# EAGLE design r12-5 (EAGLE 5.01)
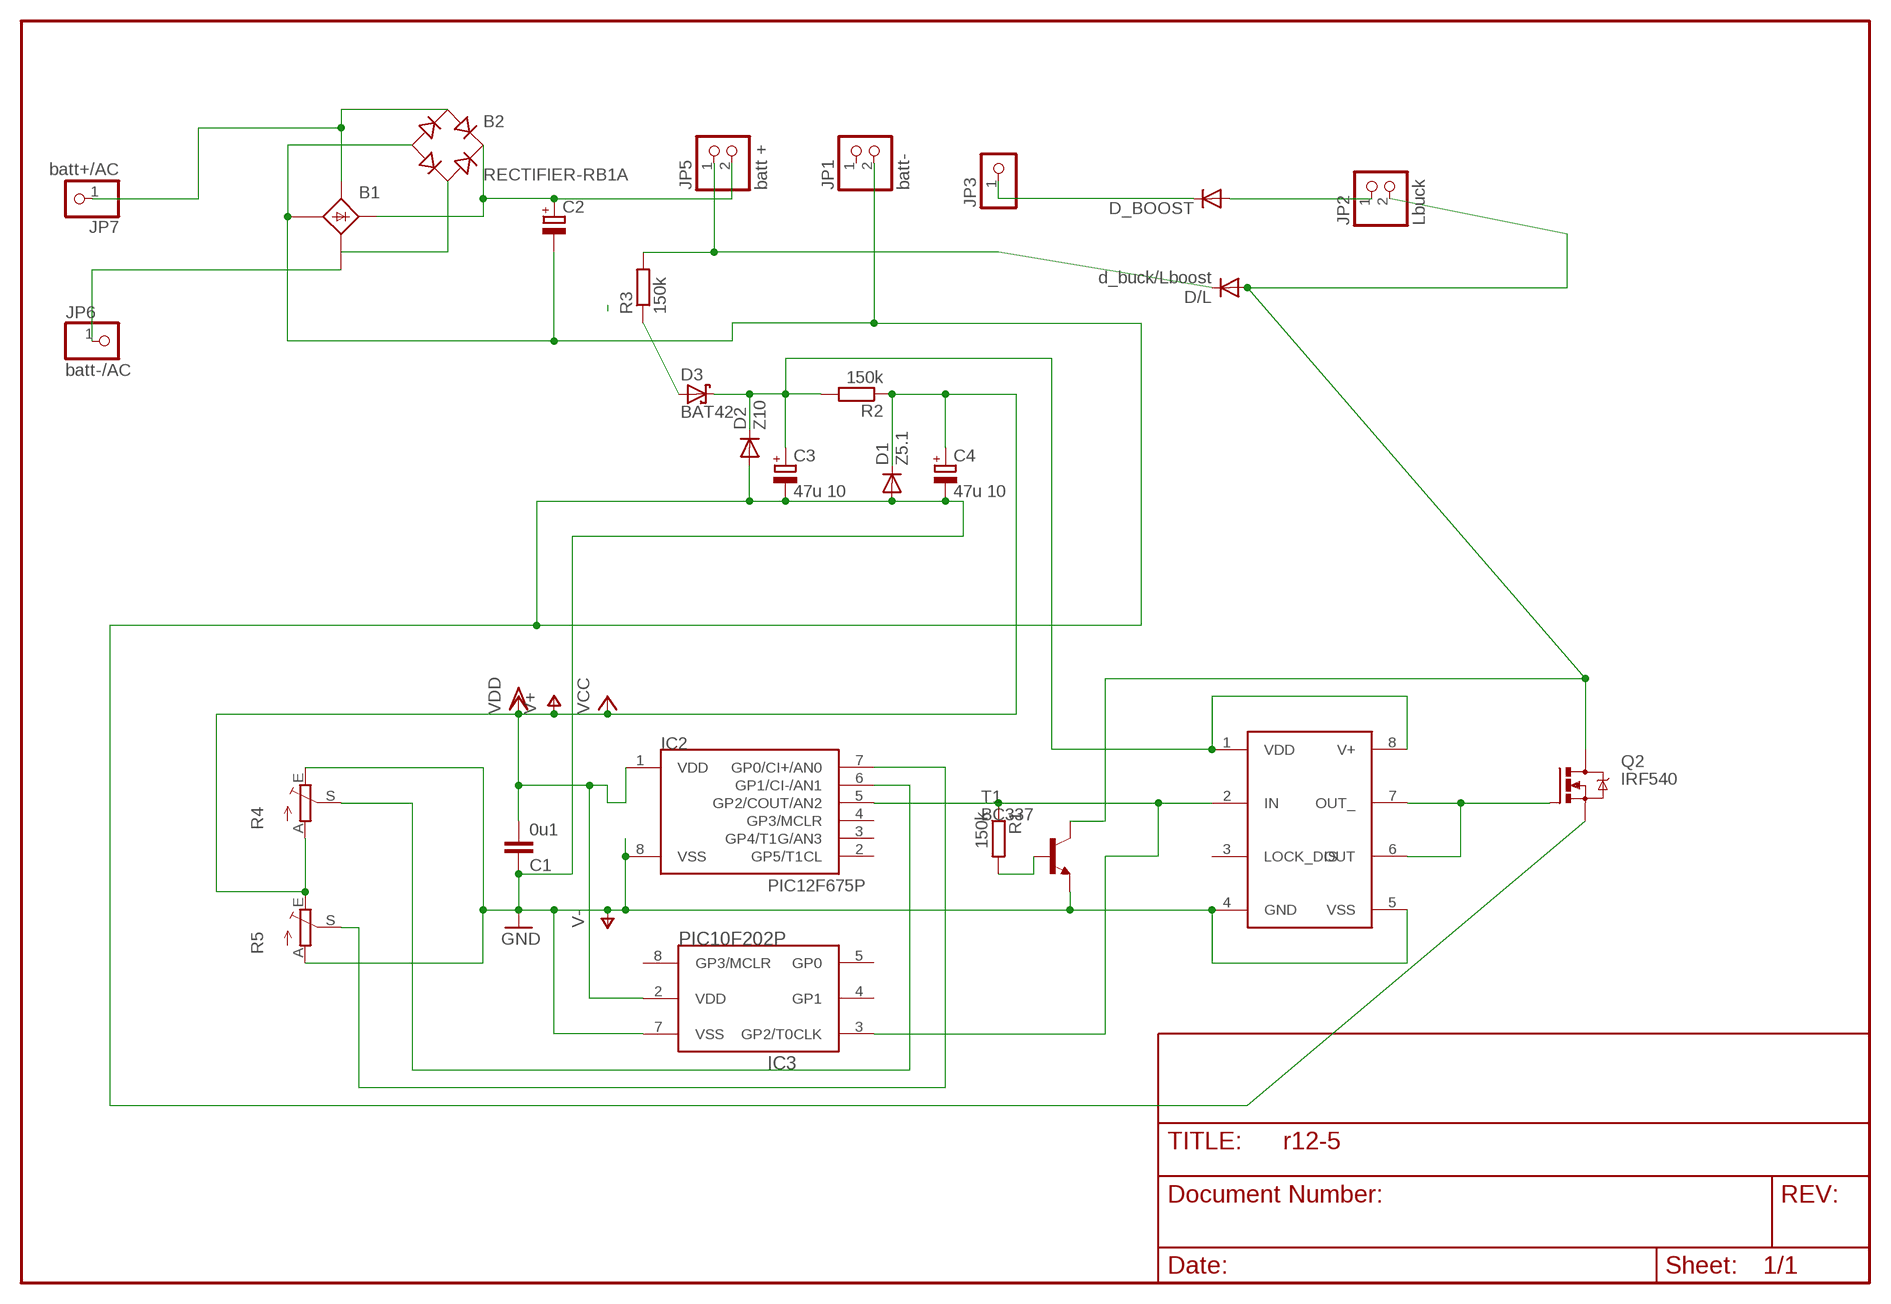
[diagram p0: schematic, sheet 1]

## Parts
B1  B25A-  [B25A-]
B2  RECTIFIER-RB1A  [RB1A]
C1  0u1  C-EU050-025X075  [C050-025X075]
C2  CPOL-EUE7.5-18  [E7,5-18]
C3  47u 10  CPOL-EUE2,5-6E  [E2,5-6E]
C4  47u 10  CPOL-EUE2.5-6  [E2,5-6]
D1  Z5.1  DIODE-D-7.5  [D-7.5]
D2  Z10  DIODE-D-7.5  [D-7.5]
D3  BAT42  [DO35-10]
D/L  d_buck/Lboost  DIODE-D-7.5  [D-7.5]
D_BOOST  DIODE-D-5  [D-5]
IC1  TC4432X  [SO-08]
IC2  PIC12F675P  [DIL8]
IC3  PIC10F202P  [DIL8]
JP1  batt-  PINHD-1X2  [1X02]
JP2  Lbuck  PINHD-1X2  [1X02]
JP3  PINHD-1X1  [1X01]
JP5  batt +  PINHD-1X2  [1X02]
JP6  batt-/AC  PINHD-1X1  [1X01]
JP7  batt+/AC  PINHD-1X1  [1X01]
Q2  IRF540  [TO220BV]
R1  150k  R-EU_0207/15  [0207/15]
R2  150k  R-EU_0204/7  [0204/7]
R3  150k  R-EU_0204/7  [0204/7]
R4  TRIM_EU-CA6V  [CA6V]
R5  TRIM_EU-CA6V  [CA6V]
T1  BC337  [TO92]

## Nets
LOAD: D_BOOST.C JP3.1
N$1: D/L.C JP5.1 R3.2
N$3: B1.AC2-(AC2) JP6.1
N$4: C3.+ D2.C D3.C IC1.1(VDD) IC1.8(V+) R2.2
N$5: D_BOOST.A JP2.1
N$6: R1.2 T1.2(B)
N$7: IC1.6(OUT) IC1.7(OUT_) Q2.G
N$8: B1.AC1 B2.AC1 JP7.1
N$9: D/L.A JP2.2 Q2.D T1.3(C)
N$10: B1.+ B2.+ C2.+ JP5.2
N$11: B1.AC2 B2.AC2
N$13: IC2.7(GP0/CI+/AN0) R5.S
N$14: IC1.2(IN) IC2.5(GP2/COUT/AN2) IC3.3(GP2/T0CLK) R1.1
N$15: IC2.6(GP1/CI-/AN1) R4.S
N$17: D3.A R3.1
V+: C1.2 C4.+ D1.C IC2.1(VDD) IC3.2(VDD) R2.1 R4.A R5.E ; supply symbol labelled VCC, VDD
V-: B1.-1(-) B2.- C1.1 C2.- C3.- C4.- D1.A D2.A IC1.4(GND) IC1.5(VSS) IC2.8(VSS) IC3.7(VSS) JP1.2 Q2.S R4.E R5.A T1.1(E) ; supply symbol labelled GND
Unconnected: B1.+1(+) B1.- B1.AC1-(AC1) IC1.3(LOCK_DIS) IC2.2(GP5/T1CL) IC2.3(GP4/T1G/AN3) IC2.4(GP3/MCLR) IC3.4(GP1) IC3.5(GP0) IC3.8(GP3/MCLR) JP1.1

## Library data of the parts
B1 = rectifier:B25A-: RECTIFIER 25-A bridge
B2 = rectifier:RECTIFIER-: Rectifier
C1 = rcl:C-EU: CAPACITOR, European symbol
C2-C4 = rcl:CPOL-EU: POLARIZED CAPACITOR, European symbol
D1 D2 D/L D_BOOST = diode:DIODE-: DIODE
D3 = diode-1:BAT42: DIODE
IC1 = microchip:TC4432
IC2 = microchip-3:PIC12F6*: uPC nW 1k Program Flash memory 2x Timer Comparator 10b A/D converter/ 4xIN
IC3 = microchip-3:PIC10F20*: uPC nW 0,25/0,5k Program Flash memory
JP1 JP2 JP5 = pinhead:PINHD-1X2: PIN HEADER
JP3 JP6 JP7 = pinhead:PINHD-1X1: PIN HEADER
Q2 = transistor-power:IRF540: HEXFET Power MOSFET
R1-R3 = rcl:R-EU_: RESISTOR, European symbol
R4 R5 = pot:TRIM_EU-: POTENTIOMETER
T1 = transistor-neu-to92:BC337: NPN TRANSISTOR

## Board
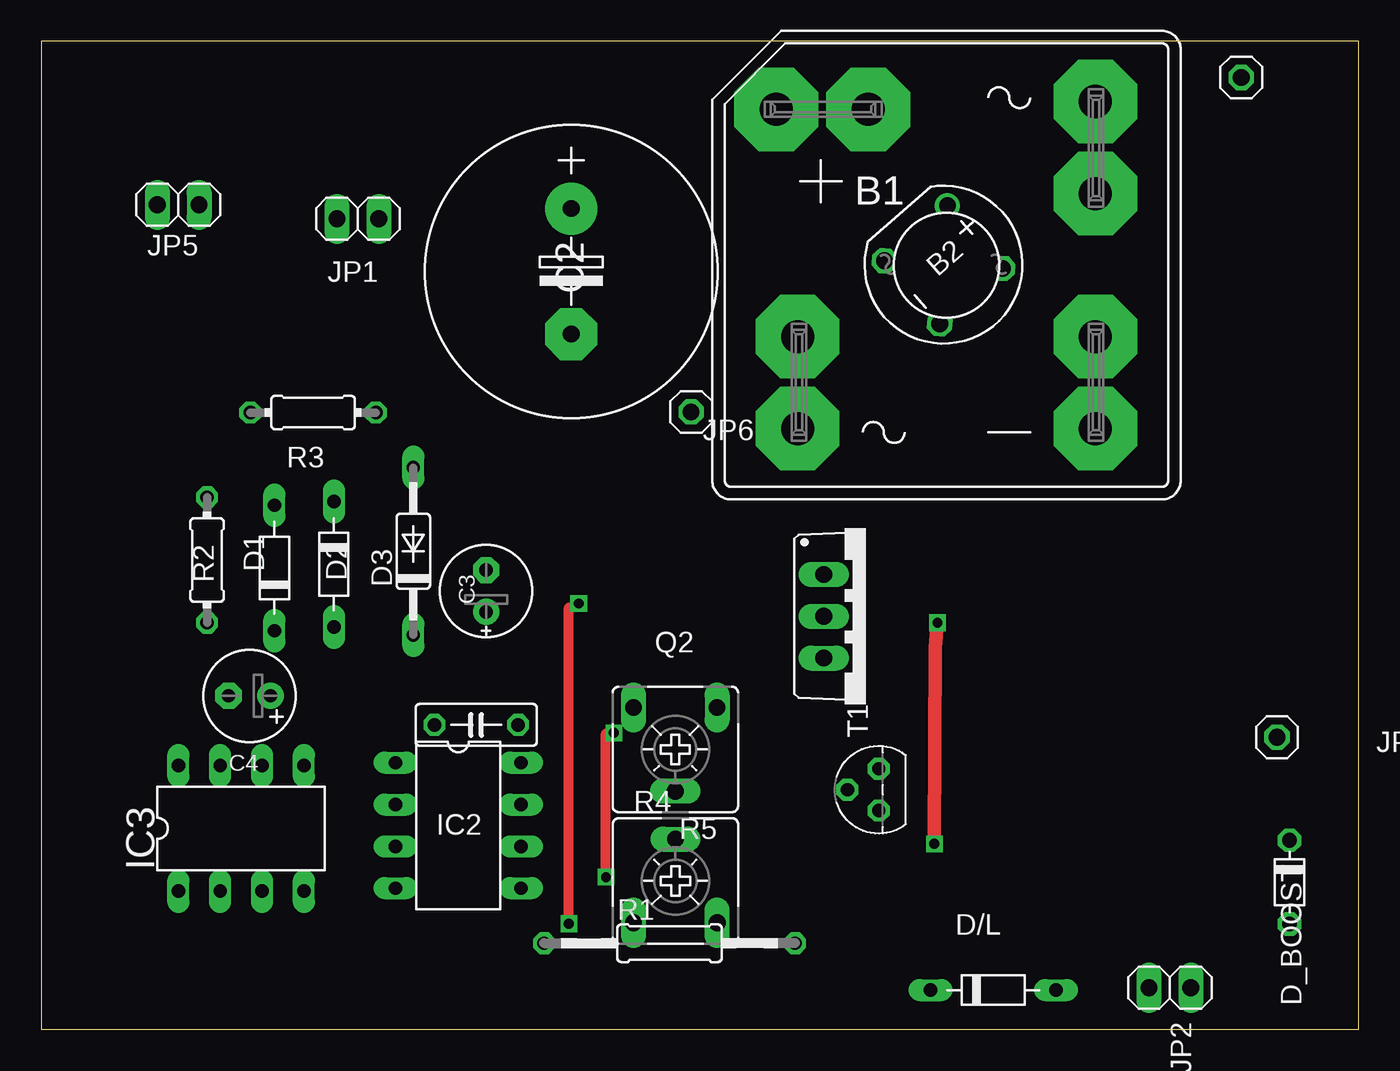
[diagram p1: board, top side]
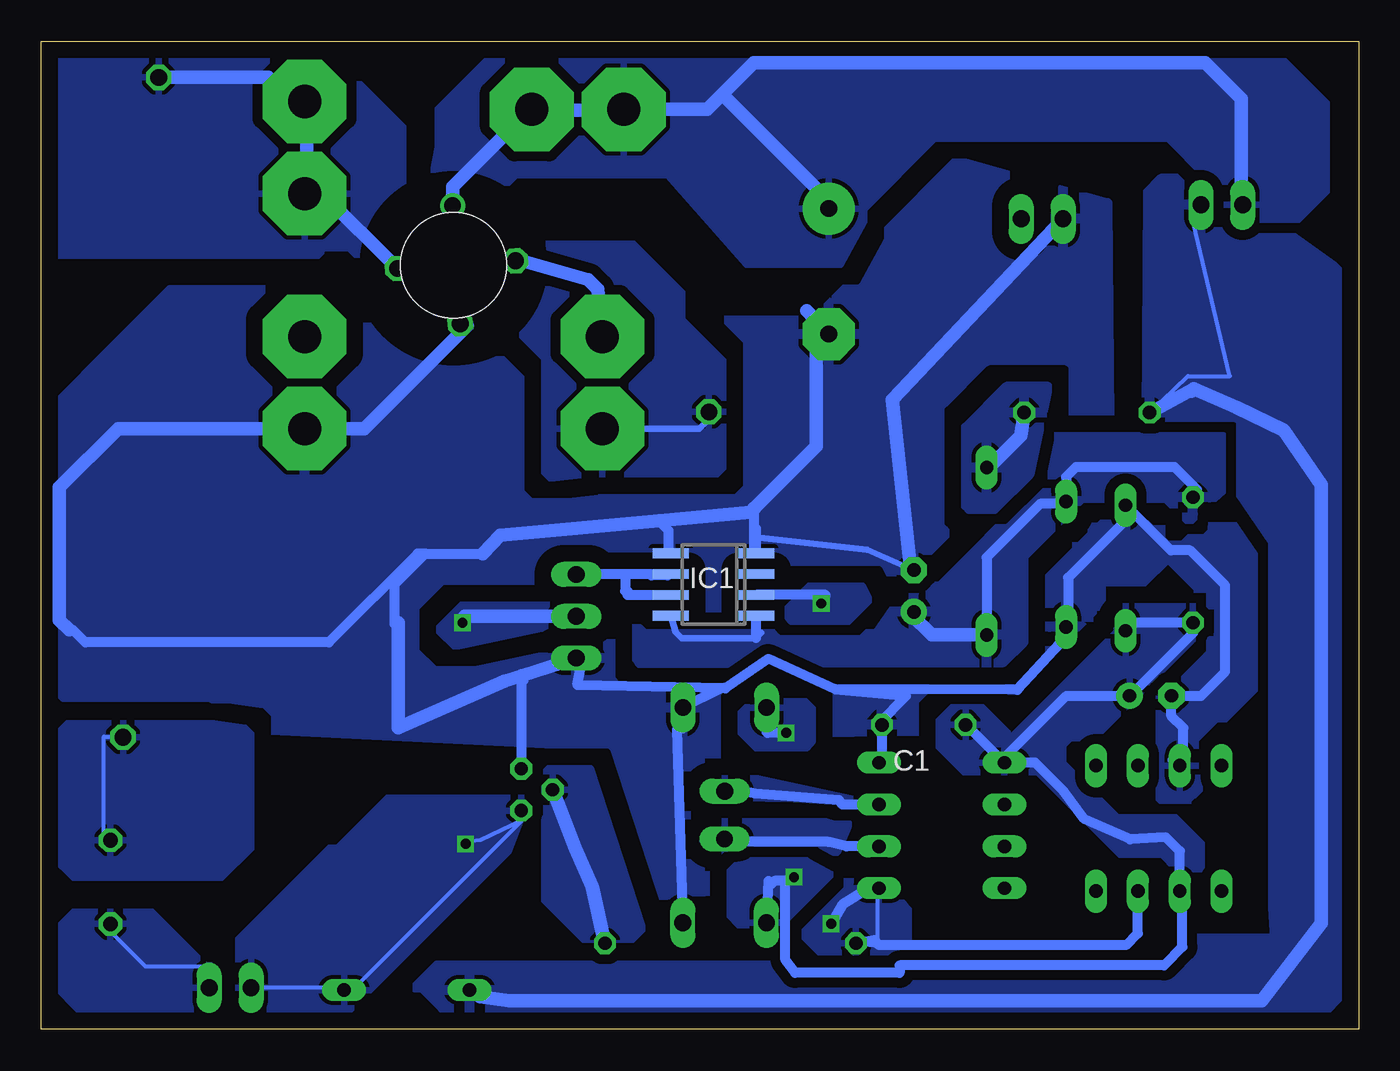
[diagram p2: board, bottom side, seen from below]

Size 80 x 60 mm. Coordinates in mm from the lower left corner, seen from the top.
Outline: 0,0 80,0 80,60 0,60 0,0
Copper layers (1*16): Top 0.035mm / dielectric 1.5mm / Bottom 0.035mm
Design rules "default": minimum track width 10mil, minimum drill 24mil, track to track 8mil, track to pad 8mil, pad to pad 8mil, via to via 8mil, smd to smd 8mil, copper to edge 40mil, drill to drill 8mil, minimum pad ring 10mil, minimum via ring 8mil, stop-mask expansion 4mil, vias tented up to drill 0mil, thermal gap 10mil

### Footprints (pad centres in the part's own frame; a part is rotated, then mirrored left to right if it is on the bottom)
B25A- = drill 2.007 pad 5.08 octagon: + -10.338,9.449; +1 -4.75,9.449; - 9.042,-4.343; -1 9.042,-9.931; AC1 9.042,4.343; AC1- 9.042,9.931; AC2 -9.042,-4.343; AC2- -9.042,-9.931 | hole 6.401: 0,0
RB1A = drill 1.016 round: + -2.54,2.54 | drill 1.016 octagon: - 2.54,-2.54; AC1 2.54,2.54; AC2 -2.54,-2.54
C050-025X075 = drill 0.813 octagon: 1 -2.54,0; 2 2.54,0
E7,5-18 = drill 1.016 pad 3.15 round: + -3.81,0 | drill 1.016 pad 3.15 octagon: - 3.81,0
E2,5-6E = drill 0.813 pad 1.575 round: + -1.27,0 | drill 0.813 pad 1.575 octagon: - 1.27,0
E2,5-6 = drill 0.813 pad 1.6 round: + -1.27,0 | drill 0.813 pad 1.6 octagon: - 1.27,0
D-7.5 = drill 0.813 long: A 3.81,0; C -3.81,0
DO35-10 = drill 0.813 long: A 5.08,0; C -5.08,0
D-5 = drill 0.9 octagon: A 2.54,0; C -2.54,0
SO-08 = smd 0.6 x 2.2: 1 -1.905,-2.6; 2 -0.635,-2.6; 3 0.635,-2.6; 4 1.905,-2.6; 5 1.905,2.6; 6 0.635,2.6; 7 -0.635,2.6; 8 -1.905,2.6
DIL8 = drill 0.813 long: 1 -3.81,-3.81; 2 -1.27,-3.81; 3 1.27,-3.81; 4 3.81,-3.81; 5 3.81,3.81; 6 1.27,3.81; 7 -1.27,3.81; 8 -3.81,3.81
1X02 = drill 1.016 long: 1 -1.27,0; 2 1.27,0
1X01 = drill 1.016 octagon: 1 0,0
TO220BV = drill 1.016 long: D 0,-2.54; G -2.54,-2.54; S 2.54,-2.54
0207/15 = drill 0.813 octagon: 1 -7.62,0; 2 7.62,0
0204/7 = drill 0.813 octagon: 1 -3.81,0; 2 3.81,0
CA6V = drill 1.016 long: A -2.54,-2.54; E 2.54,-2.54; S 0,2.54
TO92 = drill 0.813 octagon: 1 1.27,0; 2 0,1.905; 3 -1.27,0

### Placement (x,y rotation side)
B1  54.97,46.41 0 top
B2  54.79,46.43 311.3 top
C1  26.42,18.49 180 top
C2  32.18,46.02 270 top
C3  27.01,26.62 90 top
C4  12.65,20.26 180 top
D1  14.16,28.02 90 top
D2  17.77,28.24 270 top
D3  22.59,29.03 90 top
D/L  57.8,2.39 0 top
D_BOOST  75.79,8.94 270 top
IC1  39.18,27.01 90 bottom
IC2  25.32,12.38 270 top
IC3  12.14,12.2 0 top
JP1  19.23,49.21 180 top
JP2  68.53,2.53 180 top
JP3  75.03,17.74 0 top
JP5  8.32,50.06 180 top
JP6  39.46,37.49 0 top
JP7  72.86,57.8 0 top
Q2  50.05,25.08 270 top
R1  38.15,5.23 0 top
R2  10.07,28.5 90 top
R3  16.51,37.45 180 top
R4  38.51,9.02 0 top
R5  38.5,17 180 top
T1  50.85,14.55 90 top

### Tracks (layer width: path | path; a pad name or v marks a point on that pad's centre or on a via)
LOAD
  Bottom 0.254: D_BOOST.C 76.2,11.43 76.2,17.78 74.93,17.78 JP3.1
  pour Bottom: 69.52,18.59 78.41,18.59 79.34,17.67 79.34,10.46 78.07,9.19 69.02,9.19 67.26,10.96 67.26,17.96 67.61,18.31
N$1
  Bottom 0.254: JP5.1 10.16,49.53 7.84,39.66 10.38,39.66 R3.2
  Bottom 0.813: D/L.C 53.34,1.97 51.58,1.73 5.91,1.73 2.29,6.44 2.29,33.06 4.55,36.37 7.46,37.78 10.02,38.89 | 10.02,38.89 10.17,38.73 | 10.02,38.89 R3.2
  pour Bottom (isolate 0.61, rank 3): 8.95,51.64 12.01,51.64 12.83,50.83 12.9,37.01 10.08,36.31 8.46,34.33 5.22,29.62 5.22,7.4 5.09,5.5 12.42,5.5 14.05,3.87 55.98,3.87 57.3,2.55 56.91,2.55 54.56,0.2 2.96,0.2 0.3,2.86 0.3,45.12 1.52,46.34
N$3
  Bottom 0.406: JP6.1 39.04,37.49 40.06,36.47 B1.AC2-
  pour Bottom (isolate 0.61, rank 2): 46.69,33.71 38.95,33.71 38.58,34.07 38.58,40.61 41.07,43.1 41.07,44.77 44.02,47.71 51.93,47.71 52.49,47.16 52.49,43.75 49.45,40.72 49.45,33.81 49.09,33.44
N$4
  Bottom 0.406: 36.27,24.09 36.59,23.77 36.63,23.74 41.11,23.74 41.48,24.1 IC1.8
  Bottom 0.61: 10.07,32.3 10.35,32.02 | R2.2 10.07,32.3 | 10.07,32.3 9.83,32.54 9.83,32.79 11.18,34.14 17.18,34.14 17.77,33.55 D2.C 17.63,32.05 17.48,31.9 | D3.C 22.59,28.66 19.36,31.9 17.48,31.9 | 17.48,31.9 17.41,31.84 | 36.59,23.77 36.6,23.77 36.6,25.11 IC1.1
  Bottom 0.813: C3.+ 27.01,25.34 27.16,25.18 25.93,23.95 D3.C
  pour Bottom (isolate 0.61, rank 2): 8.34,32.69 8.34,35.85 8.24,35.95 19.14,35.95 19.65,35.45 19.65,32.69 25.45,26.89 27.29,26.89 29.29,24 43.32,24 43.84,24.46 43.84,22.53 43.65,22.23 21.58,22.3 20.36,23.52 20.36,28.73 16.8,32.28 11.71,32.28 10.29,30.86
N$5
  Bottom 0.254: D_BOOST.A 76.2,6.35 73.66,3.81 69.85,3.81 JP2.1
  pour Bottom: 69.23,3.89 70.02,3.89 73.27,7.14 78.07,7.14 79.55,5.65 79.55,2.97 77.29,0.71 70.71,0.71 70.43,0.99 70.43,1.05 70.43,1.13 69.72,1.84
N$6
  Bottom 0.813: R1.2 46.53,8.66 47.59,10.99 T1.2
  pour Bottom (isolate 0.61, rank 2): 46.65,15.86 49.2,15.86 49.45,15.61 49.45,7.8 47.09,5.44 44.08,5.44 43.45,6.07
N$7
  Bottom 0.61: 44.54,27.62 42.94,27.62 42.94,27.56 41.99,27.56 41.99,27.65 IC1.6 | 44.54,27.62 Q2.G | IC1.7 44.4,26.38 44.4,26.62 44.54,26.62 44.54,27.62 | 44.54,27.62 44.54,27.64
N$8
  Bottom 0.813: JP7.1 66.2,57.8 63.88,55.47 63.88,51.49 64.22,51.14 64.01,50.93 B1.AC1 62.93,50.75 B2.AC1
  pour Bottom (isolate 0.61, rank 2): 58.01,46.88 58.01,54.8 62.8,59.59 79.11,59.59 80.48,58.22 80.48,47.61 79.84,46.98 63.17,46.98 62.99,47.16 62.99,47.24 62.8,47.43 61.33,47.43 59.77,45.87 59.58,45.87 58.66,45.87 58.66,45.77 58.57,45.77 58.29,46.05
N$9  (via drill 0.6)
  Top 0.813: v54.42,24.69 54.28,23.17 v54.23,11.27
  Bottom 0.254: 50.8,12.7 53.34,11.49 54.47,11.35 v54.23,11.27 | JP2.2 67.31,2.54 62.23,2.54 D/L.A 60.96,2.54 50.8,12.7 | 50.8,12.7 T1.3
  Bottom 0.813: T1.3 50.97,13.46 | Q2.D 54.28,25.08 v54.42,24.69
  pour Bottom: 50.37,14.07 58.98,14.07 62.03,11.02 62.52,11.02 68.03,5.51 68.03,1.07 67.54,0.57 61.81,0.57 51.64,10.74
  pour Bottom: 48.39,25.79 54.48,25.79 55.82,24.46 55.82,24.12 54.89,23.19 49.59,24.32 48.74,24.74
N$10
  Bottom 0.813: 38.65,56.78 36.73,58.7 9.31,58.7 7.12,56.52 7.12,49.73 7.05,49.81 JP5.2 | 38.65,56.78 39.57,55.85 B1.+ 44.63,55.5 | B2.+ 55.02,51.15 50.35,55.82 44.74,55.82 44.23,56.33 44.23,55.89 44.63,55.5 | 44.63,55.5 44.65,55.47 | C2.+ 32.18,50.32 38.65,56.78
  pour Bottom (isolate 0.61): 55.92,53.57 55.92,55.89 52.25,59.56 5.26,59.56 1.96,56.26 1.96,50.86 3.66,49.16 8.55,49.16 9.28,49.9 9.28,51.75 11.6,54.06 25.74,54.06 30.04,49.77 30.04,49.03 31.46,46.42 37.2,46.42 42,51.85 51.14,51.85 54.69,48.31 54.69,48.32 54.57,48.44 55.31,48.44 56.64,49.77
N$11
  Bottom 0.813: B1.AC2 46.2,44.95 46.77,45.52 51.13,46.75 | 51.13,46.75 51.2,46.68 B2.AC2 | 51.13,46.75 51.04,46.84
N$13
  Bottom 0.61: IC2.7 31.36,13.65 31.55,13.92 36.65,14.31 37.47,14.5 38.61,14.66 R5.S
  pour Bottom (isolate 0.61, rank 3): 36.49,15.25 38.94,15.29 39.85,14.82 39.74,14.27 39.59,14.07 34.25,13.98 28.87,13.6
N$14  (via drill 0.6)
  Top 0.61: v32.04,6.41 32.04,25.6 v32.64,25.86
  Bottom 0.254: R1.1 29.21,5.08 29.21,8.89 IC2.5
  Bottom 0.61: 29.21,8.89 31.36,7.57 v32.04,6.41 | IC3.3 13.41,5.83 14.12,5.12 29.13,5.12 29.43,5.41 29.41,5.42 R1.1 | IC1.2 32.37,26.38 32.37,26.33 32.73,26.33 32.73,25.86 v32.64,25.86
  pour Bottom (isolate 0.61): 30.11,26.94 33.39,26.94 34.68,25.64 34.68,24.98 34.46,24.75 30.96,24.75 29.65,26.06
  pour Bottom (isolate 0.61, rank 4): 28.78,8.99 31.39,8.99 33.64,6.74 33.64,5.52 32.79,4.67 27.46,4.67 27.33,4.8 27.33,7.29 27.51,7.47
N$15
  Bottom 0.61: IC2.6 31.11,11.11 32.21,11.38 38.32,11.38 38.66,11.71 R4.S
  pour Bottom (isolate 0.61, rank 2): 30.9,12.5 31.86,12.5 32.36,12.65 39.38,12.65 39.84,11.84 39.88,11.15 39.17,10.44 31.95,10.44 31.65,10.74
N$17
  Bottom 0.813: D3.A 22.45,34.11 20.54,36.03 R3.1
  pour Bottom (isolate 0.61): 18.86,39.01 21.4,39.01 23.88,36.54 23.88,31.81 23.66,31.6 22.11,31.6 19.99,33.72
V+  (via drill 0.6)
  Top 0.61: v34.29,9.25 34.29,17.96 v34.77,18.01
  Bottom 0.61: IC2.1 19.66,16.19 17.95,14.48 16.66,12.76 13.88,11.54 11.71,11.66 10.87,10.82 IC3.2 10.81,8.39 10.65,8.24 10.71,8.19 10.71,5 11.82,3.89 27.88,3.89 27.88,3.43 34.23,3.43 34.82,4.23 34.82,9.02 | IC2.1 21.59,16.19 21.65,16.13 | D1.C 14.2,24.21 14.3,24.31 13.92,24.69 R2.1 10.07,24.07 13.88,20.26 C4.+ 17.75,20.26 21.59,16.42 21.51,16.34 IC2.1 | 23.88,18.53 23.89,18.54 | 23.88,18.53 C1.2 | IC2.1 21.54,16.19 23.88,18.53 | 34.82,9.02 v34.29,9.25 | R5.E 35.95,18.07 35.89,18.01 v34.77,18.01 | R4.A 35.85,9.02 35.66,8.83 35.47,9.02 34.82,9.02
  pour Bottom (isolate 0.61, rank 3): 9.54,25.68 14.76,25.68 14.76,25.57 14.69,24.17 21.25,17.61 21.32,18.03 23.2,19.91 24.35,19.91 25.5,18.76 25.5,17.12 23.99,15.61 19.53,15.61 14.52,10.59 11.98,10.59 11.11,9.73 9.54,9.73 9.54,11.3 11.11,12.88 14.64,12.88 17.96,16.19 17.96,17.21 17.5,17.67 16.04,17.67 9.66,24.04
  pour Bottom (isolate 0.61, rank 2): 33.16,17.49 33.16,19.49 33.58,19.91 36.87,19.91 37.53,19.25 37.53,17.98 36.61,17.07 33.52,17.07
  pour Bottom (isolate 0.61): 32,9.41 32,9.4 35.06,6.34 37.68,6.34 38.2,6.86 38.2,9.63 37.48,10.35 33.6,10.35 33.46,10.21
V-
  Bottom 0.406: C3.- 29.83,29.12 36.36,29.86
  Bottom 0.61: 10.87,15.99 10.83,15.95 | IC3.7 10.87,15.99 | 10.87,15.99 11.25,16.37 11.3,16.37 10.65,17.02 10.65,18.3 11.38,19.02 C4.- 9.58,20.26 8.12,21.72 8.12,26.96 10.24,29.08 11.42,29.08 D1.A 14.16,30.92 17.65,27.43 17.65,24.55 D2.A 17.77,23.85 20.73,20.61 31.81,20.66 | 31.81,20.66 35.87,22.5 38.46,20.7 | Q2.S 47.19,22.54 47.13,22.61 47.45,20.9 38.46,20.7 | 31.81,20.66 27.48,20.24 29.18,18.54 29.13,18.49 C1.1 28.96,16.19 | 28.96,16.19 IC2.8 | 28.96,16.19 28.78,16.02 | 41.4,18.21 41.03,18.27 R5.A | 41.4,18.21 R4.E | 41.4,18.21 41.19,18.43 41.19,19.48 38.63,20.74 38.46,20.7 | 50.81,21.48 50.81,21.29 50.72,21.2 50.85,21.07 T1.1 | 36.63,31.71 36.6,31.67 36.73,31.55 36.73,30.4 | 36.63,31.71 | 36.73,30.4 36.73,29.26 | 42.49,30.89 42.49,30.85 41.91,30.28 41.92,30.28 41.92,28.92 IC1.5 | 56.67,28.88 53.19,28.88 | 56.67,28.88 58.53,27.01 58.53,24.6 58.48,24.55 58.31,24.55 | 56.67,28.88 57.15,28.88 62.53,23.5 77.32,23.5 78.08,24.26 78.31,24.26 | 36.73,30.4 36.6,30.4 36.6,28.92 IC1.4
  Bottom 0.813: Q2.S 50.81,21.48 51.88,21.13 58.31,18.33 58.31,24.55 58.31,24.68 | 53.19,28.88 52.13,30 42.49,30.89 36.93,31.41 36.63,31.71 32.93,35.41 32.93,43.04 33.52,43.62 C2.- | C3.- 27.19,27.89 28.33,38.21 JP1.2 | 78.31,24.26 78.89,24.84 78.89,32.91 75.32,36.47 B1.-1 60.38,36.47 54.13,42.72 54.25,42.85 B2.-
  pour Bottom (isolate 1.016, rank 4): 15.27,50.16 15.16,36.94 7.7,32.54 7.7,32.4 22.35,18.15 38.91,17.93 39.07,8.41 43.27,8.04 45.72,17.16 66.08,18.15 69.74,20.18 78.64,20.18 82.56,24.1 82.56,34.51 72.17,44.89 54.22,44.89 52.39,43.07 33.1,43.07 28.82,47.35 28.82,49.44 25.29,52.97
  pour Bottom (isolate 0.61, rank 4): 10.15,13.42 11.6,13.42 12.14,13.97 12.14,21.87 11.96,22.05 11.96,22.59 9.84,24.71 9.84,26.72 11.72,28.6 11.6,28.6 9.59,30.61 7,30.61 5.96,29.57 5.96,20.94 8.08,18.82 8.62,18.82 9.89,17.55 9.89,17.49 9.89,15.48 9.65,15.24 9.65,15.13 9.65,14.52 9.89,14.27 9.96,14.21 10.02,14.21 10.39,13.84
